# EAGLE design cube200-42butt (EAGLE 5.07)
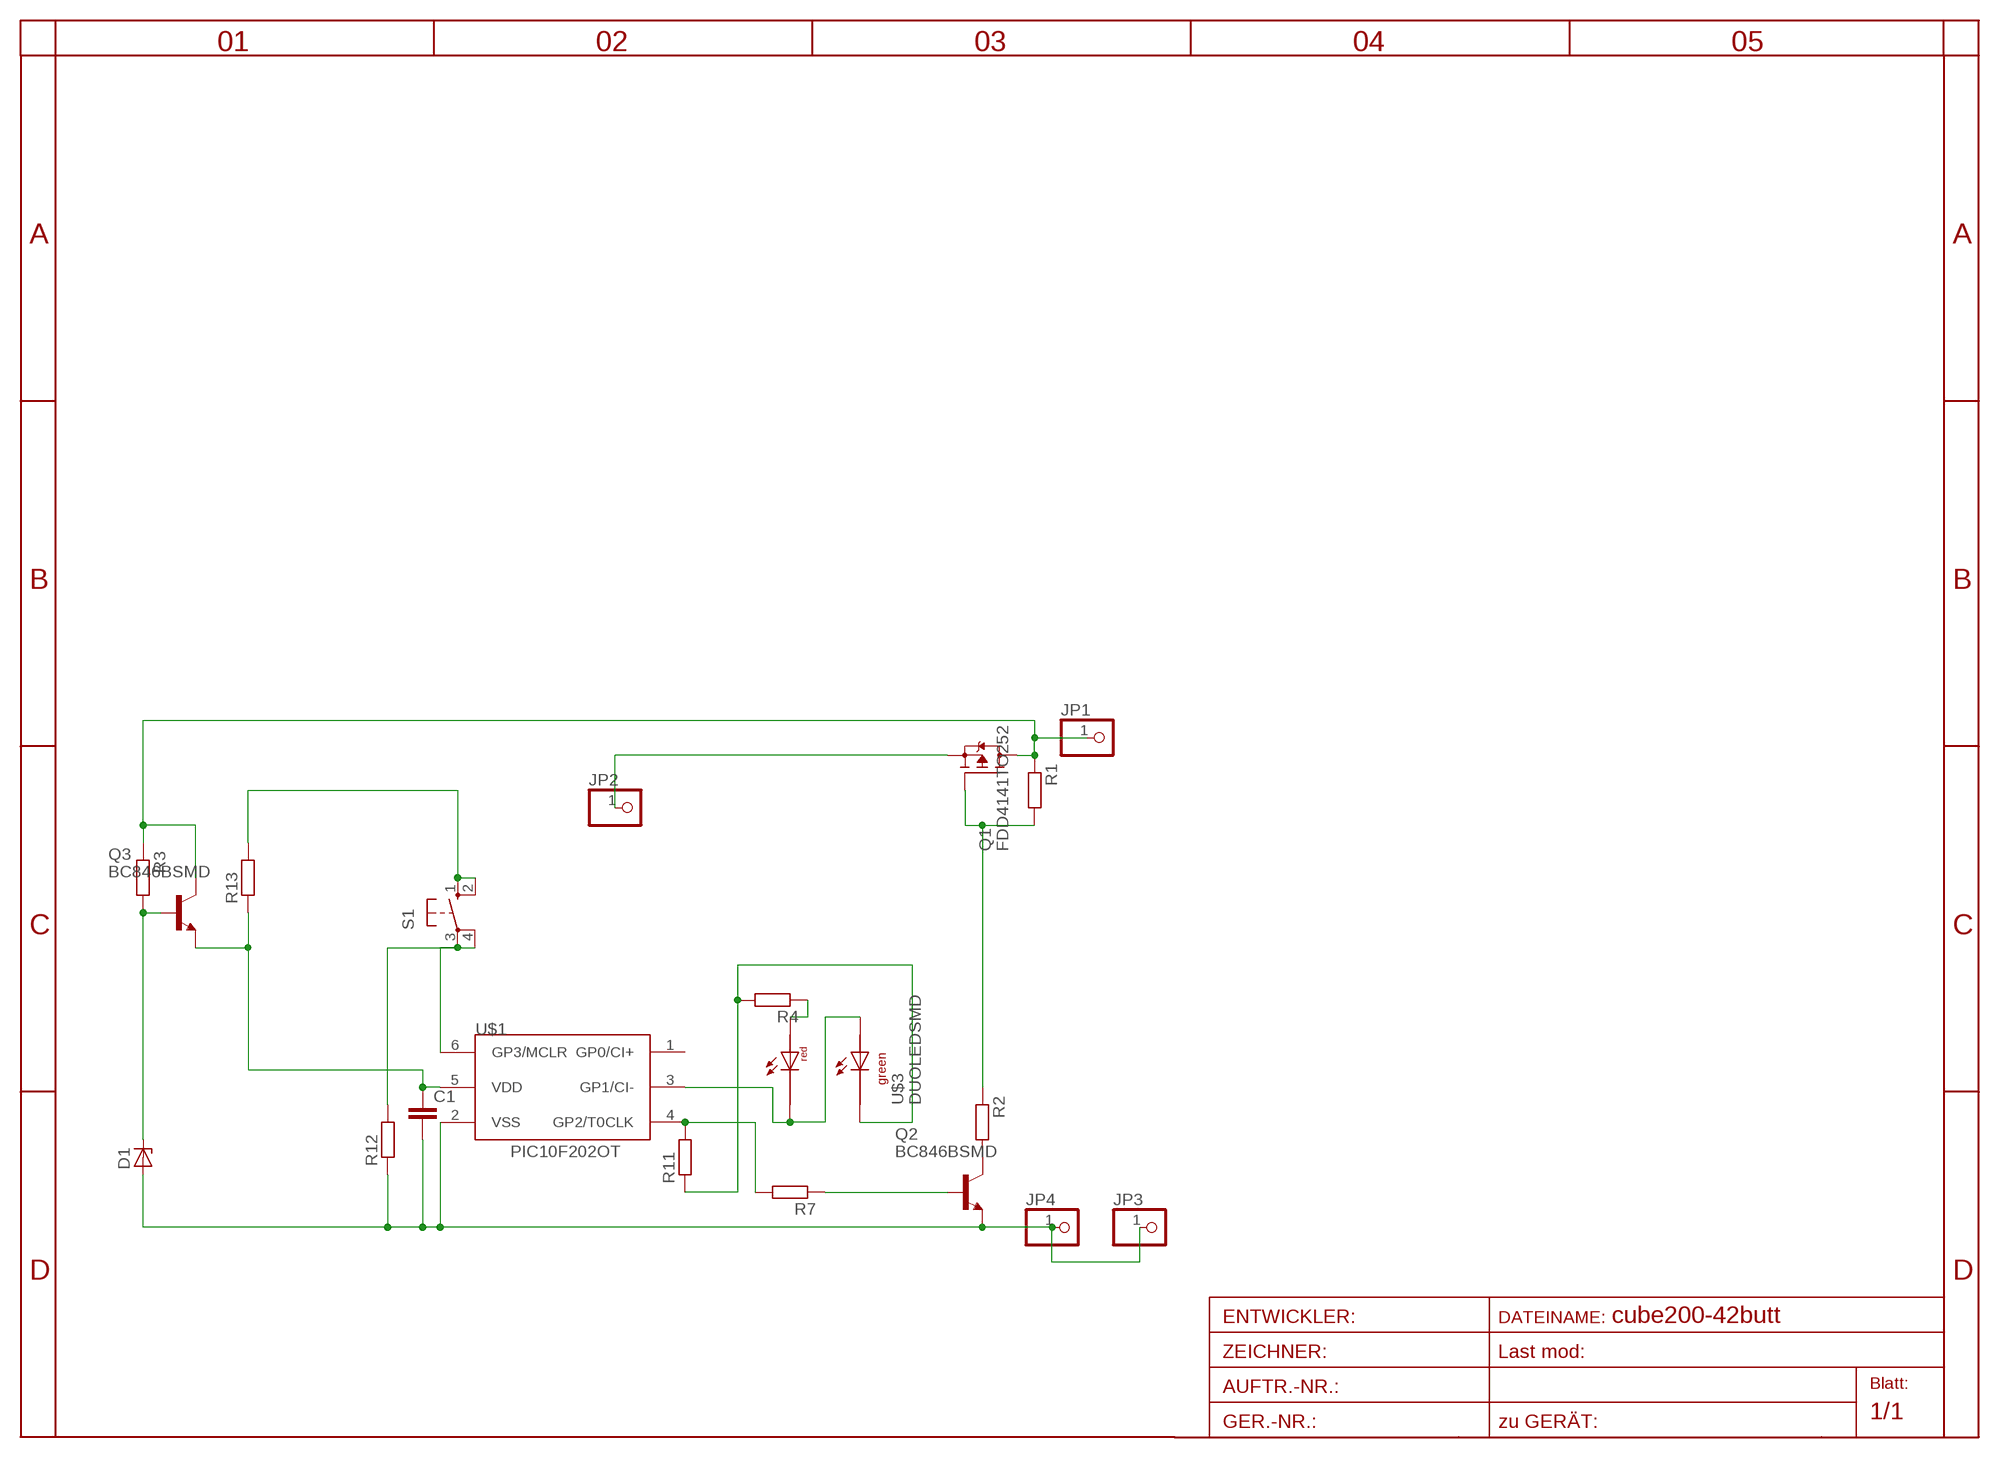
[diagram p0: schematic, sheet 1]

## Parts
C1  C-EUC1206  [C1206]
D1  ZENER-DIODESOD80C  [SOD80C]
JP1  PINHD-1X11MM6  [1X1MM8]
JP2  PINHD-1X11MM6  [1X1MM8]
JP3  PINHD-1X11MM6  [1X1MM8]
JP4  PINHD-1X11MM6  [1X1MM8]
Q1  FDD4141TO252  [TO252]
Q2  BC846BSMD  [SOT23]
Q3  BC846BSMD  [SOT23]
R1  R-EU_R0805  [R0805]
R2  R-EU_R0805  [R0805]
R3  R-EU_R0805  [R0805]
R4  R-EU_R0805  [R0805]
R7  R-EU_R1206  [R1206]
R11  R-EU_R0805  [R0805]
R12  R-EU_R0805  [R0805]
R13  R-EU_R0805  [R0805]
S1  10-XX  [B3F-10XX]
U$1  PIC10F202OT  [SOT23-6]
U$3  DUOLEDSMD  [DUOLEDSMD]

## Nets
GND: C1.2 D1.A JP3.1 JP4.1 Q2.2(E) R12.1 U$1.2(VSS)
GP2: R7.2 R11.2 U$1.4(GP2/T0CLK)
GP3: R12.2 S1.3(P) S1.4(P1) U$1.6(GP3/MCLR)
N$2: U$1.3(GP1/CI-) U$3.AGRN U$3.CRED
N$3: Q2.3(C) R2.2
N$4: D1.C Q3.1(B) R3.2
N$5: R4.1 U$3.ARED
N$6: R4.2 R11.1 U$3.CGRN
N$7: Q1.1(G) R1.2 R2.1
N$10: Q2.1(B) R7.1
N$15: R13.2 S1.1(S) S1.2(S1)
V+IN: JP1.1 Q1.2(D) Q3.3(C) R1.1 R3.1
V+OUT: JP2.1 Q1.3(S)
VDD: C1.1 Q3.2(E) R13.1 U$1.5(VDD)
Unconnected: U$1.1(GP0/CI+)

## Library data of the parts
C1 = rcl:C-EU: CAPACITOR, European symbol
D1 = diode-1:ZENER-DIODE: Z-Diode
JP1-JP4 = pinhead:PINHD-1X1: PIN HEADER
Q1 = transistor-fet:FDD4141: P-Channel PowerTrench® MOSFET Source: FDD4141.pdf
Q2 Q3 = transistor-npn:BC846*: NPN Transistor
R1-R4 R7 R11-R13 = rcl:R-EU_: RESISTOR, European symbol
S1 = switch-omron:10-XX: OMRON SWITCH
U$1 = microchip-5:PIC10F2*: uPC nW 0,25/0,5k Program Flash memory Comparator
U$3 = led:DUOLEDSMD

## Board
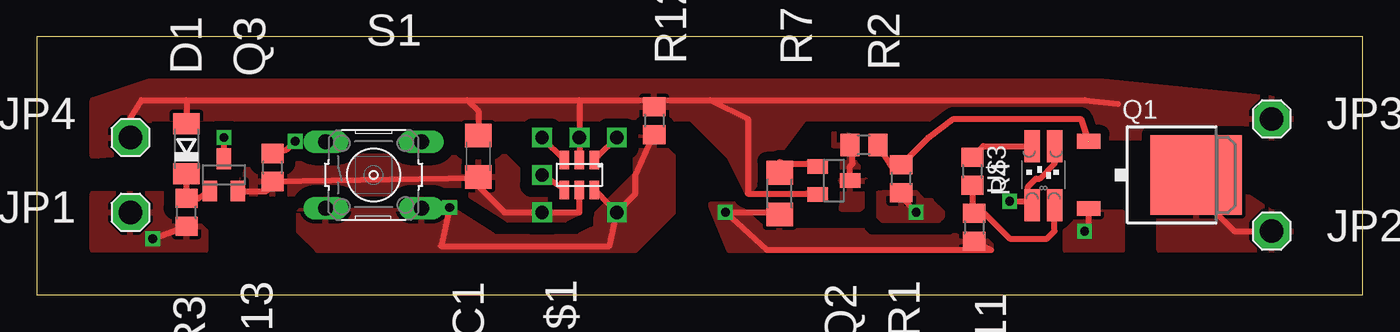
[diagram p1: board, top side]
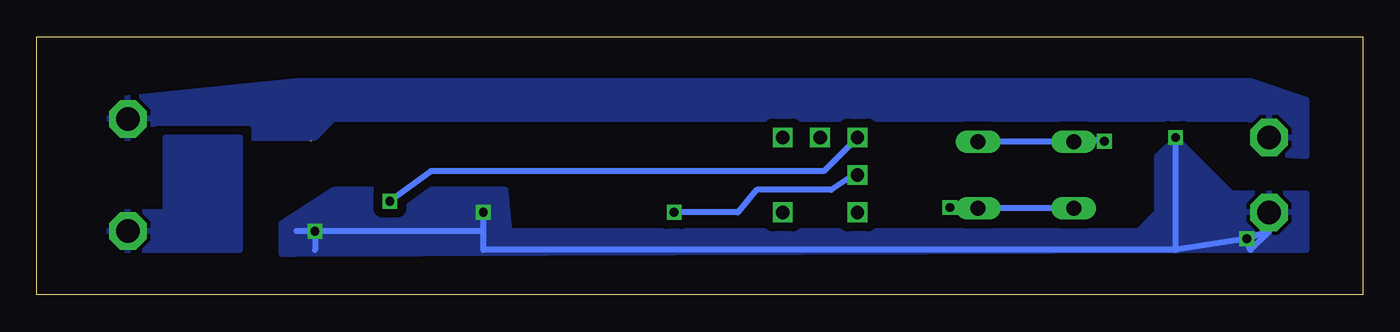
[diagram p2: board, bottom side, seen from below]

Size 90 x 17.5 mm. Coordinates in mm from the lower left corner, seen from the top.
Outline: 0,0 90,0 90,17.5 0,17.5 0,0
Copper layers (1*16): Top 0.035mm / dielectric 1.5mm / Bottom 0.035mm
Design rules "default": minimum track width 10mil, minimum drill 24mil, track to track 8mil, track to pad 8mil, pad to pad 8mil, via to via 8mil, smd to smd 8mil, copper to edge 40mil, drill to drill 8mil, minimum pad ring 10mil, minimum via ring 8mil, stop-mask expansion 4mil, vias tented up to drill 0mil, thermal gap 10mil

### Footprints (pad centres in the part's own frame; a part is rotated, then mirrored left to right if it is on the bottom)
C1206 = smd 1.6 x 1.8: 1 -1.4,0; 2 1.4,0
SOD80C = smd 1.4 x 1.8: A 1.7,0; C -1.7,0
1X1MM8 = drill 1.6 pad 2.54 octagon: 1 0,0
TO252 = smd 1 x 1.6: 1 -2.28,-4.8; 2 2.28,-4.8 | smd 5.4 x 6.2: 3 0,2.5
SOT23 = smd 1 x 1.4: 1 -0.95,-1.1; 2 0.95,-1.1; 3 0,1.1
R0805 = smd 1.3 x 1.5: 1 -0.95,0; 2 0.95,0
R1206 = smd 1.6 x 1.803: 1 -1.422,0; 2 1.422,0
B3F-10XX = drill 1.016 long: 1 -3.251,2.261; 2 3.251,2.261; 3 -3.251,-2.261; 4 3.251,-2.261
SOT23-6 = smd 0.635 x 1.27: 1 -1.016,-1.016; 2 0,-1.016; 3 1.016,-1.016; 4 1.016,1.016; 5 0,1.016; 6 -1.016,1.016
DUOLEDSMD = smd 1.067 x 2.184: AGRN 0.77,1.95; ARED -0.77,1.95; CGRN 0.77,-2.05; CRED -0.77,-2.05

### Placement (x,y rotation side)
C1  29.97,9.4 90 top
D1  10.16,9.91 90 top
JP1  6.35,5.59 0 top
JP2  83.82,4.32 0 top
JP3  83.82,11.94 0 top
JP4  6.35,10.67 0 top
Q1  76.2,8.13 270 top
Q2  54.1,7.75 270 top
Q3  12.7,8.13 0 top
R1  58.67,7.87 90 top
R2  56.13,10.16 180 top
R3  10.16,5.59 90 top
R4  63.5,8.38 270 top
R7  50.42,6.86 270 top
R11  63.63,4.57 270 top
R12  41.91,11.81 270 top
R13  16,8.64 90 top
S1  22.86,8.13 0 top
U$1  36.83,8.13 180 top
U$3  68.33,8.13 0 top

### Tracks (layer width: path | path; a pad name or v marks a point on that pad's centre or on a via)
GND  (via drill 0.9 pad 1.27)
  Top 0.406: U$1.2 v36.83,10.67 36.83,13.21 | 10.16,13.21 D1.A | 10.16,13.21 7.11,13.21 6.35,11.94 | C1.2 29.97,12.45 29.21,13.21 | 10.16,13.21 29.21,13.21 | 29.21,13.21 36.83,13.21 | Q2.2 52.26,6.86 48.26,6.86 48.26,11.94 45.72,13.21 | 36.83,13.21 41.91,13.21 | 41.91,13.21 45.72,13.21 | 73.41,12.95 71.12,13.21 45.72,13.21 | 41.91,13.21 R12.1
  pour Top (isolate 0.61, rank 3): 3.81,9.4 3.81,13.21 7.62,14.48 72.39,14.48 85.09,13.21 85.09,10.67 71.12,10.67 69.85,11.94 52.07,11.94 48.26,6.86 46.99,9.4 44.45,11.94 7.62,11.94 7.37,9.65
  pour Bottom (isolate 0.61, rank 3): 3.81,9.4 3.81,13.21 7.62,14.48 72.39,14.48 85.09,13.21 85.09,10.67 71.12,10.67 69.85,11.94 7.62,11.94 7.37,9.65
GP2  (via drill 0.6, 0.9 pad 1.27)
  Top 0.406: R11.2 64.77,3.05 49.53,3.05 v46.74,5.59 49.81,5.59 R7.2 | U$1.4 v34.29,8.13
  Bottom 0.406: v46.74,5.59 42.42,5.59 41.15,7.11 36.07,7.11 34.54,8.13 v34.29,8.13 34.29,7.87
  pour Top (isolate 0.813, rank 2): 47.5,6.1 45.72,6.1 46.99,3.05 64.77,3.05 64.77,4.32 49.53,4.32
GP3  (via drill 0.6, 0.9 pad 1.27)
  Top 0.406: v39.37,5.59 39.37,6.04 38.92,6.04 U$1.6 | v28.02,5.92 27.43,3.3 38.86,3.3 v39.37,5.59 | R12.2 41.66,10.41 40.64,8.13 40.64,6.86 v39.37,5.59
  Bottom 0.406: v28.02,5.92 S1.4 S1.3
  pour Top (isolate 0.813, rank 2): 17.78,5.59 17.78,4.32 19.05,3.05 40.64,3.05 43.18,5.59 43.18,9.4 41.91,10.67 40.64,10.67 40.64,8.13 36.83,4.32 31.75,4.32 29.21,6.86 19.05,6.86
N$1  (via drill 0.9 pad 1.27)
  Top 0.406: 38.1,9.4 v39.37,10.67
N$2  (via drill 0.6, 0.9)
  Top 0.406: U$1.3 v34.29,10.67 | v66.04,6.35 67.28,6.35 | 67.28,6.35 U$3.CRED | 67.28,6.35 67.28,7.34 67.82,7.87 68.07,7.87 69.09,8.89 69.09,10.07 U$3.AGRN
  Bottom 0.406: v34.29,10.67 36.58,8.38 63.25,8.38 v66.04,6.35
N$3
  Top 0.406: Q2.3 55.2,8.72 55.37,8.89 55.37,9.84 R2.2
  pour Top (isolate 0.813, rank 2): 55.88,10.67 55.63,10.67 54.61,10.92 54.1,10.92 54.1,6.35 54.61,5.84 55.88,5.84 56.39,6.35
N$4
  Top 0.406: D1.C R3.2 10.97,6.54 Q3.1
N$5
  Top 0.406: U$3.ARED 64.25,10.08 R4.1
N$6
  Top 0.406: U$3.CGRN 69.09,6.07 69.09,4.32 68.58,3.81 66.04,3.81 64.33,5.52 R11.1 63.5,5.65 R4.2
N$7  (1 unrouted)
  Top 0.406: R2.1 58.1,8.6 R1.2 60.52,10.67 62.23,11.94 70.87,11.94 71.38,10.41
N$10
  Top 0.406: R7.1 50.42,9.02 50.8,8.89 52.3,8.89 Q2.1
N$15  (via drill 0.6)
  Top 0.406: R13.2 16.95,9.84 v17.53,10.41
  Bottom 0.406: v17.53,10.41 19.33,10.67 S1.1 S1.2
V+IN  (via drill 0.6)
  Top 0.406: v12.7,10.67 Q3.3 | v7.87,3.81 R3.1 | R1.1 58.67,6.6 v59.69,5.59 | Q1.2 71.4,4.6 v71.12,4.32
  Bottom 0.406: 6.35,4.32 7.62,3.05 v7.87,3.81 | v7.87,3.81 12.7,3.05 | 12.7,3.05 59.69,3.05 59.69,4.32 | 12.7,3.05 v12.7,10.67 | 6.35,4.32 v7.87,3.81 | 6.35,4.32 JP1.1 | 59.69,4.32 v59.69,5.59 | 59.69,4.32 v71.12,4.32 | v71.12,4.32 72.39,4.32 | v71.12,4.32 71.12,3.05
  pour Bottom (isolate 0.61): 3.81,6.86 8.89,6.86 12.7,10.67 13.97,9.4 13.97,5.59 15.24,4.32 57.91,4.32 58.17,7.11 69.85,7.11 73.41,4.83 73.41,2.79 72.39,2.79 3.81,3.05
  pour Top (isolate 0.813): 57.15,6.86 57.15,5.33 57.4,5.08 61.21,5.08 61.47,5.33 61.47,5.59 60.71,6.35 60.2,6.35 59.44,7.11
  pour Top (isolate 0.813): 3.81,6.86 8.89,6.86 11.43,4.32 11.43,3.05 3.81,3.05
  pour Top: 73.66,5.59 73.66,3.05 69.85,3.05 69.85,4.32 71.12,5.59
V+OUT
  Top 0.406: JP2.1 81.28,4.32 78.74,6.86 78.74,8.09 Q1.3
  pour Bottom: 81.28,5.59 85.09,5.59 85.09,3.05 76.2,3.05 76.2,10.67 81.28,10.67
  pour Top: 83.82,5.59 85.09,5.59 85.09,3.05 76.2,3.05 76.2,6.86 77.47,8.13 80.01,8.13
VDD  (via drill 0.9 pad 1.27)
  Top 0.406: Q3.2 15.6,7.03 R13.1 29.91,7.94 C1.1 29.97,7.37 31.75,5.59 v34.29,5.59 36.83,5.59 U$1.5
  pour Top (isolate 0.813): 13.97,8.13 15.24,9.4 31.75,9.4 34.29,6.86 35.56,6.86 36.83,5.59 35.81,5.08 32,5.08 29.21,6.86 13.97,6.86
